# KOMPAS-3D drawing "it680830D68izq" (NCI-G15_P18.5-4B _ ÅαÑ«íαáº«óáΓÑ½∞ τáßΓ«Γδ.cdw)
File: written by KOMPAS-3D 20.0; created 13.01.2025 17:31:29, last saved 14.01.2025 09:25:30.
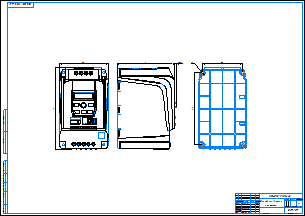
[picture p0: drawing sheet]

Sheet 1: A1, landscape

Document properties: Полное имя файла: P:\INSTART\Технический отдел\ОР\Прочие задачи\КД на номенклатурный ряд\КД на типоразмеры ПЧ\NCI\NCI-G15_P18.5-4B\NCI-G15_P18.5-4B _ Преобразователь частоты.cdw; Автор: admin

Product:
- Part/product: it680830D68izq
    source file: ..\NCI-G11_P15-4B\NCI-G11_P15-4B _ Преобразователь частоты.cdw

Title block, sheet 1: Наименование: Преобразователь / частоты; designation: NCI-G15/P18.5-4B; Количество листов документа: 1; organisation: INSTART; cell 10: Согласовано; Форматы листов документа: A1; stored path: P:\INSTART\Технический отдел\ОР\Прочие задачи\КД на номенклатурный ряд\КД на типоразмеры ПЧ\NCI\NCI-G11_P15-4B\NCI-G11_P15-4B _ Преобразователь частоты.cdw; Разработал: Уралов Д.А.; Проверил: Андреев Н.В.; Подписал: Смелков Ж.Е.; Утвердил: Ефремов И.Н.; Разработал, date: 13.01.25

Referenced files in C:\Уралов Работа\Уралов (локальная)\ПЧ\! Китай 3Д-модель NCI\NCI 11-15 4B\: NCI 11-15 4B.m3d
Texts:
  Поверхности
  it680830D68izq
  it680830D68izq it680830D68izq
Dimensions and other numbers on the sheet: 1:1; 1; 13.01.25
